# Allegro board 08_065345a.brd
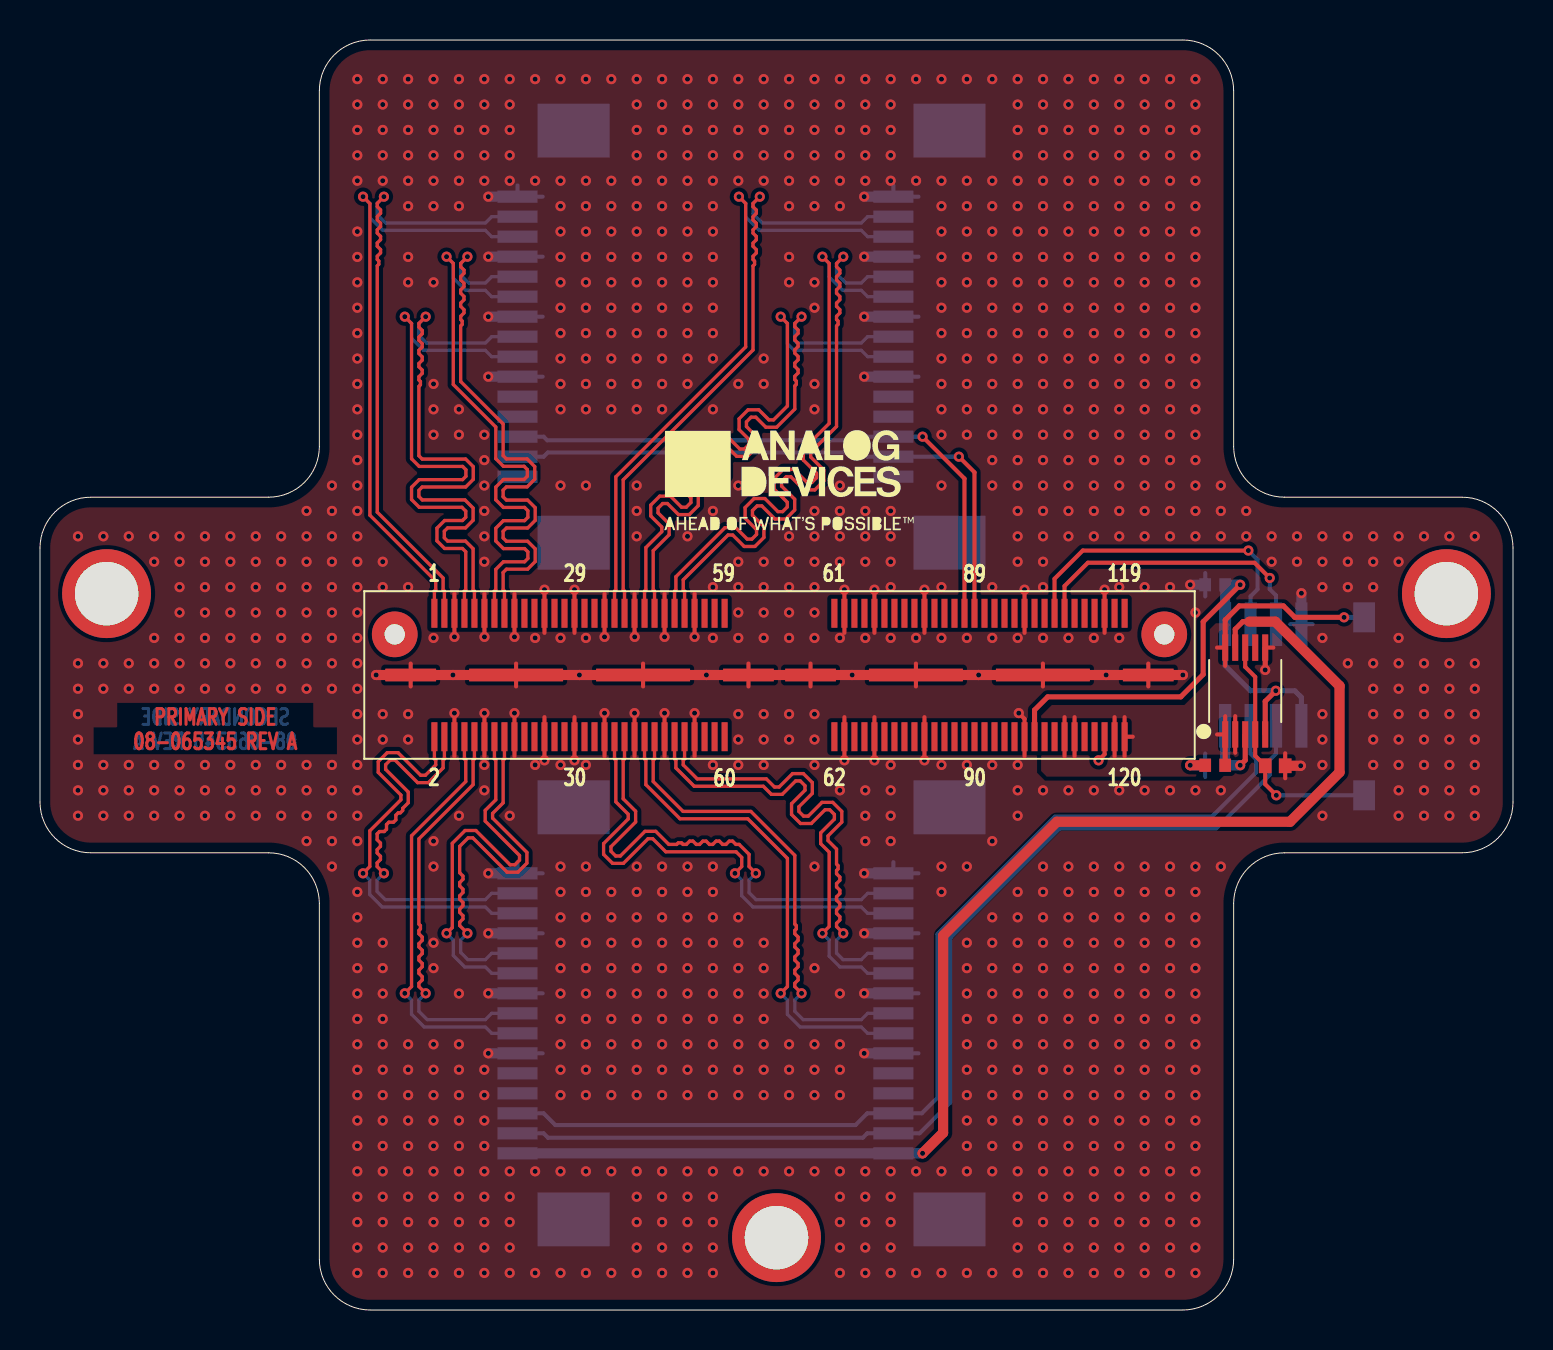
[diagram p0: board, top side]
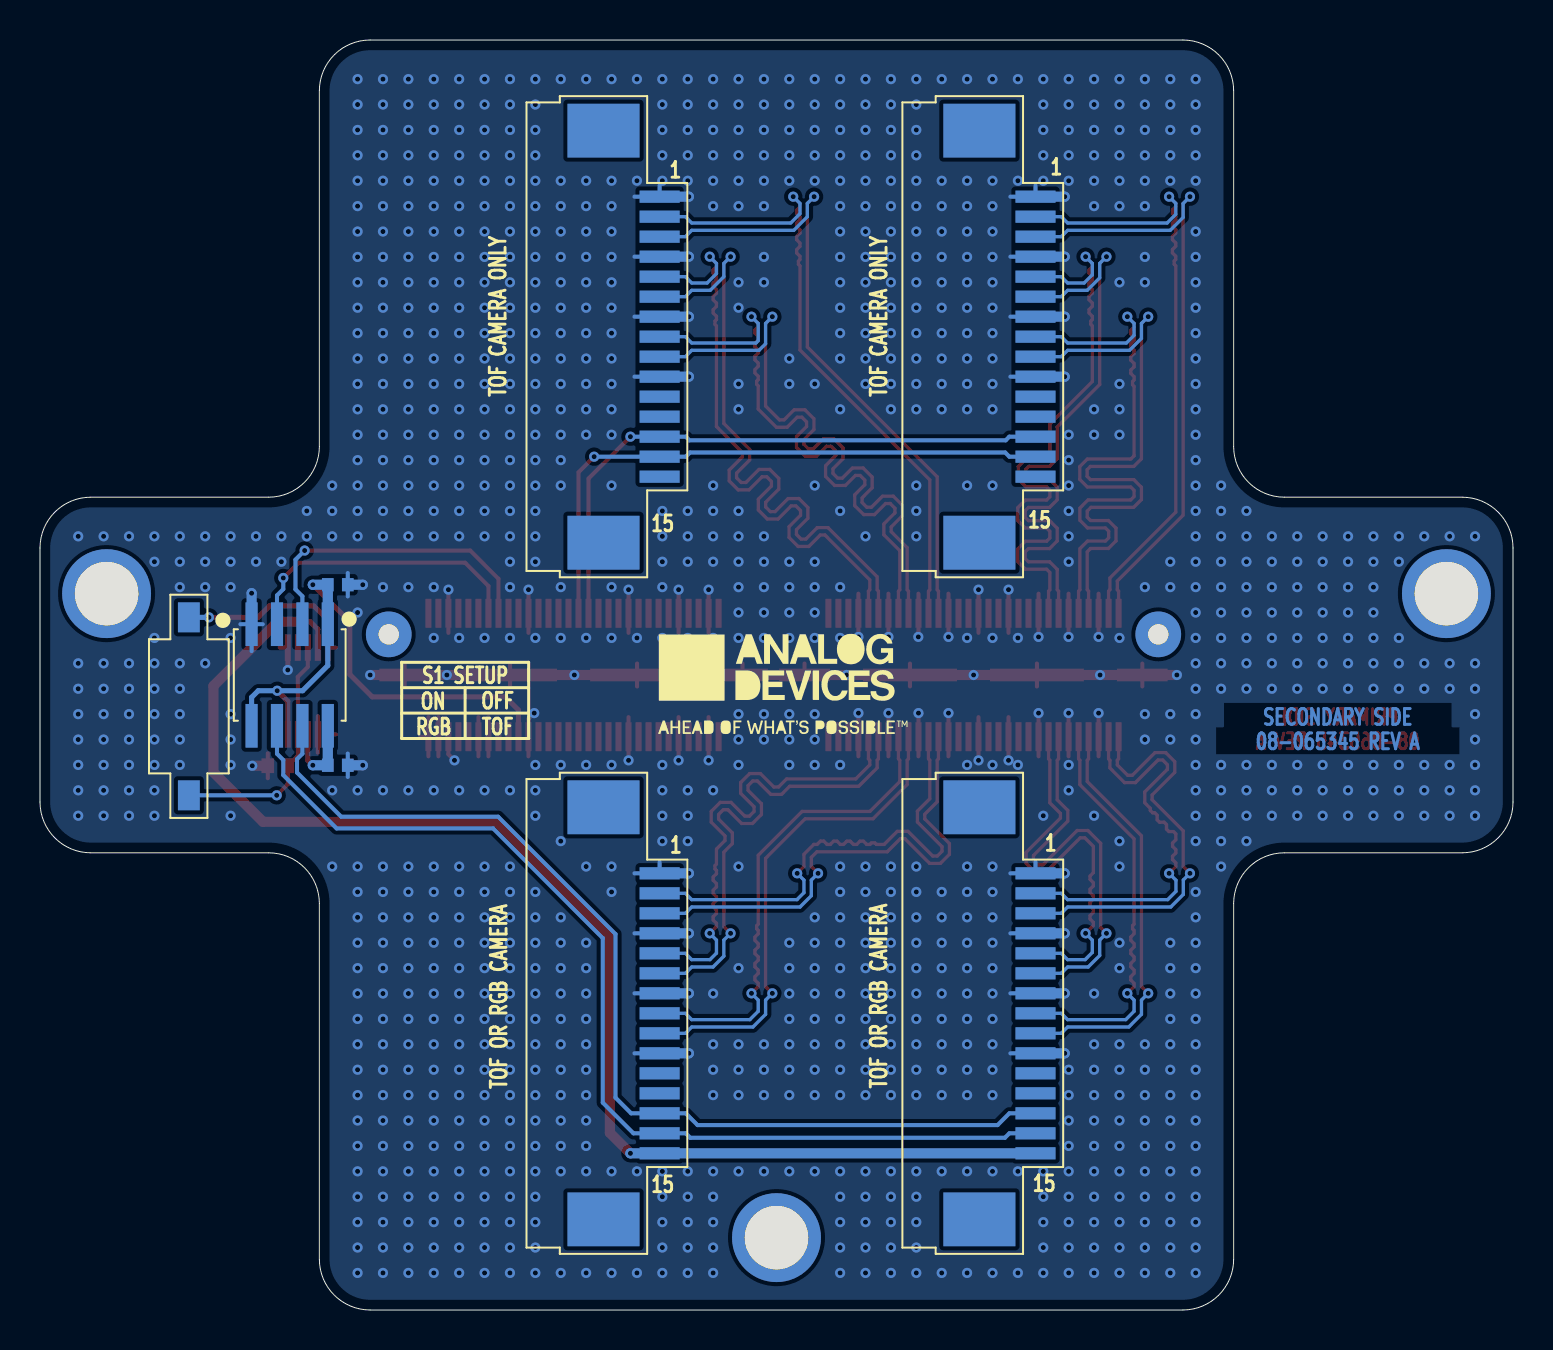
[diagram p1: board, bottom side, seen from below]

Outline 73.66 x 63.5 mm; copper layers: TOP, L2_GND, L3_GND, BOTTOM. Coordinates in mm from the lower left corner of the outline.
Outline path: 0,38.1 0,25.4 arc(0.74,23.6) 2.54,22.86 11.43,22.86 arc(13.23,22.12) 13.97,20.32 13.97,2.54 arc(14.71,0.74) 16.51,0 57.15,0 arc(58.95,0.74) 59.69,2.54 59.69,20.32 arc(60.43,22.12) 62.23,22.86 71.12,22.86 arc(72.92,23.6) 73.66,25.4 73.66,38.1 arc(72.92,39.9) 71.12,40.64 62.23,40.64 arc(60.43,41.38) 59.69,43.18 59.69,60.96 arc(58.95,62.76) 57.15,63.5 16.51,63.5 arc(14.71,62.76) 13.97,60.96 13.97,43.18 arc(13.23,41.38) 11.43,40.64 2.54,40.64 arc(0.74,39.9) 0,38.1

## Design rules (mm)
constraint set DEFAULT: min track width 0.203
net group CSI_0: nets CSI_0_CLK_N CSI_0_CLK_P CSI_0_D0_N CSI_0_D0_P CSI_0_D1_N CSI_0_D1_P
net group CSI_1: nets CSI_1_CLK_N CSI_1_CLK_P CSI_1_D0_N CSI_1_D0_P CSI_1_D1_N CSI_1_D1_P
net group CSI_4: nets CSI_4_CLK_N CSI_4_CLK_P CSI_4_D0_N CSI_4_D0_P CSI_4_D1_N CSI_4_D1_P
net group CSI_6: nets CSI_6_CLK_N CSI_6_CLK_P CSI_6_D0_N CSI_6_D0_P CSI_6_D1_N CSI_6_D1_P

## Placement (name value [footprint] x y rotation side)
C1  0.1UF  [C0402]  58.77 27.24 0 bottom
C2  0.1UF  [C0402]  58.77 36.26 180 bottom
C3  0.1UF  [C0402]  58.77 27.24 0 top
NOREF  -  [unnamed]  70.33 35.82 0 top
NOREF#2  -  [#2]  -39.37 318.77 0 top
NOREF#3  -  [#2]  73.66 22.86 90 top
NOREF#4  -  [#2]  406.4 71.12 0 top
NOREF#5  -  [#2]  73.66 40.64 180 top
NOREF#6  -  [#2]  142.24 74.93 270 top
NOREF#7  -  [unnamed]  36.83 3.62 0 top
NOREF#8  -  [#2]  -223.52 -132.08 0 top
NOREF#9  -  [#2]  406.4 10.16 0 top
NOREF#10  -  [#2]  0 40.64 270 top
NOREF#11  -  [#2]  37.16 41.45 0 top
NOREF#12  -  [#2]  -223.52 -132.08 0 top
NOREF#13  -  [unnamed]  3.33 35.82 0 top
NOREF#14  -  [#2]  -223.52 -132.08 0 top
NOREF#15  -  [#2]  142.24 113.03 0 top
NOREF#16  -  [#2]  0 22.86 0 top
NOREF#17  -  [#2]  87.63 293.37 0 top
NOREF#18  -  [#2]  176.53 318.77 0 top
NOREF#19  -  [#2]  36.8 31.27 180 bottom
NOREF#20  -  [#2]  145.43 306.07 180 bottom
NOREF#21  -  [#2]  157.49 26.04 180 bottom
P1  QTH-060-01-F-D-A  [CNSAMTECQTH-060-01-L-D-A]  36.98 31.75 0 top
P2  1-84952-5  [CNTE1-84952-5]  27.58 48.67 270 bottom
P3  1-84952-5  [CNTE1-84952-5]  46.38 48.67 270 bottom
P4  1-84952-5  [CNTE1-84952-5]  46.38 14.83 270 bottom
P5  1-84952-5  [CNTE1-84952-5]  27.58 14.83 270 bottom
R1  10K  [R0402]  61.77 27.21 0 top
S1  A6S-1104-H  [SWSML137W244H177]  66.22 30.18 0 bottom
U1  NLSX4373DR2G  [SO8]  61.17 31.75 0 bottom
U2  ADG884BRMZ  [RM10]  60.27 30.95 0 top

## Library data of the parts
C1-C3 = CAP: User Part Number: UPN; Tolerance: 10; alternate symbols: (); part number: CAP_SM-0.1UF,16V,10,E028141,C0402; tolerance: 10
P1 = CN120P_ODD_EVEN_8GND: Tolerance: N/A; User Part Number: UPN; alternate symbols: (); part number: CN120P_ODD_EVEN_8GND_SM-QTH-060-01-F-D-A,E025712,CNSAMTECQTH-060-01-L-D-A; tolerance: N/A
P2-P5 = CN15P: User Part Number: UPN; Tolerance: N/A; alternate symbols: (); part number: CN15P_SM-1-84952-5,E026042,CNTE1-84952-5; tolerance: N/A
R1 = RES: User Part Number: UPN; Tolerance: 1; alternate symbols: (R0402L,R0402L_ALT); part number: RES_SM-10K,E003751,1/10W,1,R0402; tolerance: 1
S1 = SWSPST2PIN_V4: User Part Number: UPN; Tolerance: N/A; alternate symbols: (); part number: SWSPST2PIN_V4_SM-A6S-1104-H,E025110,SWSML137W244H177; tolerance: N/A
U1 = ICNLSX4373: Tolerance: N/A; User Part Number: UPN; alternate symbols: (); part number: ICNLSX4373_SM-NLSX4373DR2G,E021744,SO8; tolerance: N/A
U2 = ADG884_V2: Tolerance: N/A; User Part Number: UPN; alternate symbols: (); part number: ADG884_V2_SM-ADG884BRMZ,E014585,RM10; tolerance: N/A

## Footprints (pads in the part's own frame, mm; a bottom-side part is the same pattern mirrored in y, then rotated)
C0402
  rect 0.584x0.66 smd: 1(-0.5,0) 2(0.5,0)
CNSAMTECQTH-060-01-L-D-A
  round 2.286 hole 1.016 unplated: (-19.241,2.032) (19.241,2.032)
  rect 0.305x1.448 smd: 1(-17.257,3.086) 2(-17.257,-3.086) 3(-16.756,3.086) 4(-16.756,-3.086) 5(-16.256,3.086) 6(-16.256,-3.086) 7(-15.756,3.086) 8(-15.756,-3.086) 9(-15.255,3.086) 10(-15.255,-3.086) 11(-14.755,3.086) 12(-14.755,-3.086) 13(-14.254,3.086) 14(-14.254,-3.086) 15(-13.754,3.086) 16(-13.754,-3.086) 17(-13.254,3.086) 18(-13.254,-3.086) 19(-12.753,3.086) 20(-12.753,-3.086) 21(-12.253,3.086) 22(-12.253,-3.086) 23(-11.753,3.086) 24(-11.753,-3.086) 25(-11.252,3.086) 26(-11.252,-3.086) 27(-10.752,3.086) 28(-10.752,-3.086) 29(-10.251,3.086) 30(-10.251,-3.086) 31(-9.751,3.086) 32(-9.751,-3.086) 33(-9.251,3.086) 34(-9.251,-3.086) 35(-8.75,3.086) 36(-8.75,-3.086) 37(-8.25,3.086) 38(-8.25,-3.086) 39(-7.75,3.086) 40(-7.75,-3.086) 41(-7.249,3.086) 42(-7.249,-3.086) 43(-6.749,3.086) 44(-6.749,-3.086) 45(-6.248,3.086) 46(-6.248,-3.086) 47(-5.748,3.086) 48(-5.748,-3.086) 49(-5.248,3.086) 50(-5.248,-3.086) 51(-4.747,3.086) 52(-4.747,-3.086) 53(-4.247,3.086) 54(-4.247,-3.086) 55(-3.747,3.086) 56(-3.747,-3.086) 57(-3.246,3.086) 58(-3.246,-3.086) 59(-2.746,3.086) 60(-2.746,-3.086) 61(2.746,3.086) 62(2.746,-3.086) 63(3.246,3.086) 64(3.246,-3.086) 65(3.747,3.086) 66(3.747,-3.086) 67(4.247,3.086) 68(4.247,-3.086) 69(4.747,3.086) 70(4.747,-3.086) 71(5.248,3.086) 72(5.248,-3.086) 73(5.748,3.086) 74(5.748,-3.086) 75(6.248,3.086) 76(6.248,-3.086) 77(6.749,3.086) 78(6.749,-3.086) 79(7.249,3.086) 80(7.249,-3.086) 81(7.75,3.086) 82(7.75,-3.086) 83(8.25,3.086) 84(8.25,-3.086) 85(8.75,3.086) 86(8.75,-3.086) 87(9.251,3.086) 88(9.251,-3.086) 89(9.751,3.086) 90(9.751,-3.086) 91(10.251,3.086) 92(10.251,-3.086) 93(10.752,3.086) 94(10.752,-3.086) 95(11.252,3.086) 96(11.252,-3.086) 97(11.753,3.086) 98(11.753,-3.086) 99(12.253,3.086) 100(12.253,-3.086) 101(12.753,3.086) 102(12.753,-3.086) 103(13.254,3.086) 104(13.254,-3.086) 105(13.754,3.086) 106(13.754,-3.086) 107(14.254,3.086) 108(14.254,-3.086) 109(14.755,3.086) 110(14.755,-3.086) 111(15.255,3.086) 112(15.255,-3.086) 113(15.756,3.086) 114(15.756,-3.086) 115(16.256,3.086) 116(16.256,-3.086) 117(16.756,3.086) 118(16.756,-3.086) 119(17.257,3.086) 120(17.257,-3.086)
  rect 2.54x0.635 smd: PAD1(-18.443,0) PAD4(-1.552,0) PAD5(1.552,0) PAD8(18.443,0)
  rect 4.699x0.635 smd: PAD2(-13.172,0) PAD3(-6.822,0) PAD6(6.822,0) PAD7(13.172,0)
CNTE1-84952-5
  rect 2.692x3.607 smd: (-10.301,0.897) (10.301,0.897)
  rect 0.61x2.007 smd: 1(-7,3.703) 2(-6,3.703) 3(-5,3.703) 4(-4,3.703) 5(-3,3.703) 6(-2,3.703) 7(-1,3.703) 8(0,3.703) 9(1,3.703) 10(2,3.703) 11(3,3.703) 12(4,3.703) 13(5,3.703) 14(6,3.703) 15(7,3.703)
R0402
  rect 0.635x0.737 smd: 1(-0.5,0) 2(0.5,0)
RM10
  rect 0.305x1.321 smd: 1(-1,-2.171) 2(-0.5,-2.171) 3(0,-2.171) 4(0.5,-2.171) 5(1,-2.171) 6(1,2.171) 7(0.5,2.171) 8(0,2.171) 9(-0.5,2.171) 10(-1,2.171)
SO8
  rect 0.61x2.184 smd: 1(-1.905,-2.54) 2(-0.635,-2.54) 3(0.635,-2.54) 4(1.905,-2.54) 5(1.905,2.54) 6(0.635,2.54) 7(-0.635,2.54) 8(-1.905,2.54)
SWSML137W244H177
  rect 1.092x1.499 smd: 1A(0,-4.449) 1B(0,4.449)
unnamed
  round 4.445 hole 3.175 unplated: (0,0)

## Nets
GND: C1.1 C2.2(N2) C3.1 P1.5 P1.6 P1.11 P1.12 P1.17 P1.18 P1.23 P1.24 P1.29 P1.30 P1.35 P1.36 P1.41 P1.42 P1.47 P1.48 P1.53 P1.54 P1.63 P1.64 P1.69 P1.70 P1.79 P1.80 P1.99 P1.100 P1.115 P1.116 P1.PAD1 P1.PAD2 P1.PAD3 P1.PAD4 P1.PAD5 P1.PAD6 P1.PAD7 P1.PAD8 P2.1 P2.4 P2.7 P2.10 P3.1 P3.4 P3.7 P3.10 P4.1 P4.4 P4.7 P4.10 P5.1 P5.4 P5.7 P5.10 R1.2(N2) U1.4 U2.6
VDD_1V8: C2.1 P1.102 U1.1(VL) U1.5 U2.5
VDD_3V3: C3.2(N2) P1.108 P1.110 P1.118 P1.120 S1.1A U2.1(VDD) U2.2 U2.10
CAM_3V3: P4.15 P5.15 U2.9
CSI_0_CLK_N: P1.9 P2.8
CSI_0_CLK_P: P1.7 P2.9(N9)
CSI_0_D0_N: P1.3 P2.2
CSI_0_D0_P: P1.1 P2.3
CSI_0_D1_N: P1.15 P2.5
CSI_0_D1_P: P1.13 P2.6
CSI_1_CLK_N: P1.10 P5.8
CSI_1_CLK_P: P1.8 P5.9(N9)
CSI_1_D0_N: P1.4 P5.2
CSI_1_D0_P: P1.2 P5.3
CSI_1_D1_N: P1.16 P5.5
CSI_1_D1_P: P1.14 P5.6
CSI_4_CLK_N: P1.45 P3.8
CSI_4_CLK_P: P1.43 P3.9(N9)
CSI_4_D0_N: P1.39 P3.2
CSI_4_D0_P: P1.37 P3.3
CSI_4_D1_N: P1.51 P3.5
CSI_4_D1_P: P1.49 P3.6
CSI_6_CLK_N: P1.46 P4.8
CSI_6_CLK_P: P1.44 P4.9(N9)
CSI_6_D0_N: P1.40 P4.2
CSI_6_D0_P: P1.38 P4.3
CSI_6_D1_N: P1.52 P4.5
CSI_6_D1_P: P1.50 P4.6
GP2_SCL: P1.87 P2.13 P3.13
GP2_SDA: P1.89 P2.14 P3.14
GP4_SCL: P1.105 U1.2
GP4_SDA: P1.107 U1.3
SCL: P4.13 P5.13 U1.7
SDA: P4.14 P5.14 U1.6
UNNAMED_2_ADG884V2_I42_D1: C1.2(N2) U1.8 U2.3
UNNAMED_2_ADG884V2_I42_IN1: R1.1 S1.1B(N2) U2.4 U2.8

Pads without a net: P1 19 20 21 22 25 26 27 28 31 32 33 34 55 56 57 58 59 60 61 62 65 66 67 68 71 72 73 74 75 76 77 78 81 82 83 84 85 86 88 90 91 92 93 94 95 96 97 98 101 103 104 106 109 111 112 113 114 117 119; P2 11 12 15; P3 11 12 15; P4 11 12; P5 11 12; U2 7

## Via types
v1: diameter 0.508, hole 0.254, TOP to BOTTOM, 1166 vias

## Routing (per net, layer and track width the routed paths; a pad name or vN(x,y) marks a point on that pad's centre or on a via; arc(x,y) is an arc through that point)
GND: length 167.1
  TOP w0.203: 43.8,32.32 P1.PAD6 43.8,31.18 ; 20.72,35.81 P1.5 v1(20.72,33.66) ; v1(41.73,36.02) P1.69 41.73,33.86 ; v1(25.23,36.02) P1.23 25.23,33.86 ; 35.43,31.18 P1.PAD4 35.43,32.32 ; 38.53,31.18 P1.PAD5 38.53,32.32 ; 53.24,33.86 P1.115 v1(53.24,36.02) ; 50.15,31.18 P1.PAD7 50.15,32.32 ; 30.16,32.32 P1.PAD3 30.16,31.18 ; v1(22.23,29.84) P1.12 22.23,27.69 ; v1(40.23,27.48) P1.64 40.23,29.64 ; v1(44.23,36.02) P1.79 44.23,33.86 ; P1.116 53.24,27.79 v1(52.93,27.48) ; 26.73,29.64 P1.30 v1(26.73,27.48) ; v1(31.23,29.84) P1.48 31.23,27.69 ; 29.73,35.81 P1.41 29.73,33.87 29.74,33.86 v1(29.74,33.66) ; 44.23,29.64 P1.80 v1(44.23,27.48) ; v1(29.73,29.84) P1.42 29.73,27.69 ; 31.23,35.81 P1.47 v1(31.23,33.66) ; 23.73,35.81 P1.17 v1(23.73,33.66) ; 23.81,31.18 P1.PAD2 23.81,32.32 ; 41.73,29.64 P1.70 v1(41.73,27.48) ; 32.73,27.69 P1.54 v1(32.73,29.84) ; 55.42,32.32 P1.PAD8 55.42,31.18 ; v1(23.73,29.84) P1.18 23.73,27.69 ; v1(48.95,29.84) 49.23,29.56 P1.100 49.23,27.69 ; 32.73,35.81 P1.53 v1(32.73,33.66) ; v1(22.23,33.66) P1.11 22.23,35.81 ; v1(28.23,29.84) P1.36 28.23,27.69 ; 25.23,29.64 P1.24 v1(25.23,27.48) ; v1(40.23,36.02) P1.63 40.23,33.86 ; v1(20.72,29.84) P1.6 20.72,27.69 ; 18.54,32.32 P1.PAD1 18.54,31.18 ; v1(28.23,33.66) P1.35 28.23,35.81 ; 26.73,33.86 P1.29 v1(26.73,36.02) ; 49.23,33.86 P1.99 v1(49.23,36.02) ; 62.27,26.59 R1.2 62.27,27.83 ; U2.6 61.68,33.12
  TOP w0.254: U2.6 v1(61.27,32)
  TOP w0.508: v1(57.15,31.75) P1.PAD8 v1(53.31,31.75) P1.PAD7 v1(46.94,31.75) P1.PAD6 v1(40.61,31.75) P1.PAD5 P1.PAD4 v1(33.32,31.75) P1.PAD3 v1(26.97,31.75) P1.PAD2 v1(20.65,31.75) P1.PAD1 v1(16.81,31.75) ; C3.1 v1(57.52,27.24) ; R1.2 v1(63.04,27.21)
  BOTTOM w0.203: 23.88,56.23 P2.1 25.14,55.67 ; 58.27,26.65 C3.1 58.27,27.82 ; 58.27,36.85 C2.2 58.27,35.68 ; 43.93,55.67 P3.1 42.67,56.23 ; P4.7 43.93,15.83 ; P5.10 25.14,12.83 ; U1.4 63.64,34.29 ; U1.4 62.52,34.29 ; U1.4 63.08,32.94 ; P5.4 25.14,18.83 ; P5.7 25.14,15.83 ; P3.10 43.93,46.67 ; P4.4 43.93,18.83 ; P2.7 25.14,49.67 ; P4.10 43.93,12.83 ; 43.93,21.83 P4.1 42.67,22.39 ; P2.4 25.14,52.67 ; P3.7 43.93,49.67 ; P3.4 43.93,52.67 ; P2.10 25.14,46.67 ; 25.14,21.83 P5.1 23.88,22.39
  BOTTOM w0.508: U1.4 v1(63.08,35.84) ; P3.1 v1(41.21,55.67) ; P2.1 v1(22.42,55.67) ; P2.4 v1(22.42,52.67) ; P4.10 v1(41.21,12.83) ; P2.10 v1(22.42,46.67) ; P4.4 v1(41.21,18.83) ; P5.4 v1(22.42,18.83) ; P4.7 v1(41.21,15.83) ; P2.7 v1(22.42,49.67) ; P3.7 v1(41.21,49.67) ; P3.10 v1(41.21,46.67) ; C3.1 v1(57.52,27.24) ; P5.10 v1(22.42,12.83) ; P5.1 v1(22.42,21.83) ; C2.2 v1(57.52,36.26) ; P4.1 v1(41.21,21.83) ; P5.7 v1(22.42,15.83) ; P3.4 v1(41.21,52.67)
  vias: v1(1.9,38.68) v1(1.9,32.33) v1(1.9,31.06) v1(1.9,29.79) v1(1.9,28.52) v1(1.9,27.25) v1(1.9,25.98) v1(1.9,24.71) v1(3.17,38.68) v1(3.17,32.33) v1(3.17,31.06) v1(3.17,27.25) v1(3.17,25.98) v1(3.17,24.71) v1(4.44,38.68) v1(4.44,32.33) v1(4.44,31.06) v1(4.44,27.25) v1(4.44,25.98) v1(4.44,24.71) v1(5.71,38.68) v1(5.71,37.41) v1(5.71,33.6) v1(5.71,32.33) v1(5.71,31.06) v1(5.71,27.25) v1(5.71,25.98) v1(5.71,24.71) v1(6.98,38.68) v1(6.98,37.41) v1(6.98,36.14) v1(6.98,34.87) v1(6.98,33.6) v1(6.98,32.33) v1(6.98,31.06) v1(6.98,27.25) v1(6.98,25.98) v1(6.98,24.71) v1(8.25,38.68) v1(8.25,37.41) v1(8.25,36.14) v1(8.25,34.87) v1(8.25,33.6) v1(8.25,32.33) v1(8.25,31.06) v1(8.25,27.25) v1(8.25,25.98) v1(8.25,24.71) v1(9.52,38.68) v1(9.52,37.41) v1(9.52,36.14) v1(9.52,34.87) v1(9.52,33.6) v1(9.52,32.33) v1(9.52,31.06) v1(9.52,27.25) v1(9.52,25.98) v1(9.52,24.71) v1(10.79,38.68) v1(10.79,37.41) v1(10.79,36.14) v1(10.79,34.87) v1(10.79,33.6) v1(10.79,32.33) v1(10.79,31.06) v1(10.79,27.25) v1(10.79,25.98) v1(10.79,24.71) v1(12.06,38.68) v1(12.06,37.41) v1(12.06,36.14) v1(12.06,34.87) v1(12.06,33.6) v1(12.06,32.33) v1(12.06,31.06) v1(12.06,27.25) v1(12.06,25.98) v1(12.06,24.71) v1(13.33,39.95) v1(13.33,38.68) v1(13.33,37.41) v1(13.33,36.14) v1(13.33,34.87) v1(13.33,33.6) v1(13.33,32.33) v1(13.33,31.06) v1(13.33,27.25) v1(13.33,25.98) v1(13.33,24.71) v1(13.33,23.44) v1(14.6,41.22) v1(14.6,39.95) v1(14.6,38.68) v1(14.6,37.41) v1(14.6,36.14) v1(14.6,34.87) v1(14.6,33.6) v1(14.6,32.33) v1(14.6,31.06) v1(14.6,27.25) v1(14.6,25.98) v1(14.6,24.71) v1(14.6,23.44) v1(14.6,22.17) v1(15.87,61.54) v1(15.87,60.27) v1(15.87,59) v1(15.87,57.73) v1(15.87,56.46) v1(15.87,53.92) v1(15.87,52.65) v1(15.87,51.38) v1(15.87,50.11) v1(15.87,48.84) v1(15.87,47.57) v1(15.87,46.3) v1(15.87,45.03) v1(15.87,43.76) v1(15.87,42.49) v1(15.87,41.22) v1(15.87,39.95) v1(15.87,38.68) v1(15.87,37.41) v1(15.87,36.14) v1(15.87,34.87) v1(15.87,33.6) v1(15.87,32.33) v1(15.87,31.06) v1(15.87,29.79) v1(15.87,28.52) v1(15.87,27.25) v1(15.87,25.98) v1(15.87,24.71) v1(15.87,23.44) v1(15.87,20.9) v1(15.87,19.63) v1(15.87,18.36) v1(15.87,17.09) v1(15.87,15.82) v1(15.87,14.55) v1(15.87,13.28) v1(15.87,12.01) v1(15.87,10.74) v1(15.87,9.47) v1(15.87,8.2) v1(15.87,6.93) v1(15.87,5.66) v1(15.87,4.39) v1(15.87,3.12) v1(15.87,1.85) v1(17.14,61.54) v1(17.14,60.27) v1(17.14,59) v1(17.14,57.73) v1(17.14,56.46) v1(17.14,37.41) v1(17.14,36.14) v1(17.14,29.79) v1(17.14,28.52) v1(17.14,18.36) v1(17.14,17.09) v1(17.14,15.82) v1(17.14,14.55) v1(17.14,13.28) v1(17.14,12.01) v1(17.14,10.74) v1(17.14,9.47) v1(17.14,8.2) v1(17.14,6.93) v1(17.14,5.66) v1(17.14,4.39) v1(17.14,3.12) v1(17.14,1.85) v1(18.41,61.54) v1(18.41,60.27) v1(18.41,59) v1(18.41,57.73) v1(18.41,56.46) v1(18.41,55.19) v1(18.41,52.65) v1(18.41,51.38) v1(18.41,36.14) v1(18.41,29.79) v1(18.41,28.52) v1(18.41,13.28) v1(18.41,12.01) v1(18.41,10.74) v1(18.41,9.47) v1(18.41,8.2) v1(18.41,6.93) v1(18.41,5.66) v1(18.41,4.39) v1(18.41,3.12) v1(18.41,1.85) v1(19.68,61.54) v1(19.68,60.27) v1(19.68,59) v1(19.68,57.73) v1(19.68,56.46) v1(19.68,55.19) v1(19.68,51.38) v1(19.68,46.3) v1(19.68,45.03) v1(19.68,43.76) v1(19.68,33.6) v1(19.68,23.44) v1(19.68,22.17) v1(19.68,18.36) v1(19.68,17.09) v1(19.68,13.28) v1(19.68,12.01) v1(19.68,10.74) v1(19.68,9.47) v1(19.68,8.2) v1(19.68,6.93) v1(19.68,5.66) v1(19.68,4.39) v1(19.68,3.12) v1(19.68,1.85) v1(20.95,61.54) v1(20.95,60.27) v1(20.95,59) v1(20.95,57.73) v1(20.95,56.46) v1(20.95,55.19) v1(20.95,45.03) v1(20.95,43.76) v1(20.95,24.71) v1(20.95,15.82) v1(20.95,13.28) v1(20.95,12.01) v1(20.95,10.74) v1(20.95,9.47) v1(20.95,8.2) v1(20.95,6.93) v1(20.95,5.66) v1(20.95,4.39) v1(20.95,3.12) v1(20.95,1.85) v1(22.22,61.54) v1(22.22,60.27) v1(22.22,59) v1(22.22,57.73) v1(22.22,56.46) v1(22.22,43.76) v1(22.22,42.49) v1(22.22,41.22) v1(22.22,39.95) v1(22.22,38.68) v1(22.22,37.41) v1(22.22,27.25) v1(22.22,25.98) v1(22.22,12.01) v1(22.22,10.74) v1(22.22,9.47) v1(22.22,8.2) v1(22.22,6.93) v1(22.22,5.66) v1(22.22,4.39) v1(22.22,3.12) v1(22.22,1.85) v1(23.49,61.54) v1(23.49,60.27) v1(23.49,59) v1(23.49,57.73) v1(23.49,56.46) v1(23.49,24.71) v1(23.49,6.93) v1(23.49,5.66) v1(23.49,4.39) v1(23.49,3.12) v1(23.49,1.85) v1(24.76,61.54) v1(24.76,56.46) v1(24.76,33.6) v1(24.76,27.25) v1(24.76,6.93) v1(24.76,1.85) v1(26.03,61.54) v1(26.03,56.46) v1(26.03,55.19) v1(26.03,53.92) v1(26.03,52.65) v1(26.03,51.38) v1(26.03,50.11) v1(26.03,48.84) v1(26.03,47.57) v1(26.03,46.3) v1(26.03,45.03) v1(26.03,41.22) v1(26.03,33.6) v1(26.03,27.25) v1(26.03,22.17) v1(26.03,20.9) v1(26.03,19.63) v1(26.03,18.36) v1(26.03,17.09) v1(26.03,15.82) v1(26.03,14.55) v1(26.03,13.28) v1(26.03,12.01) v1(26.03,10.74) v1(26.03,6.93) v1(26.03,1.85) v1(27.3,61.54) v1(27.3,56.46) v1(27.3,55.19) v1(27.3,53.92) v1(27.3,52.65) v1(27.3,51.38) v1(27.3,50.11) v1(27.3,48.84) v1(27.3,47.57) v1(27.3,46.3) v1(27.3,45.03) v1(27.3,41.22) v1(27.3,33.6) v1(27.3,27.25) v1(27.3,22.17) v1(27.3,20.9) v1(27.3,19.63) v1(27.3,18.36) v1(27.3,17.09) v1(27.3,15.82) v1(27.3,14.55) v1(27.3,13.28) v1(27.3,12.01) v1(27.3,10.74) v1(27.3,6.93) v1(27.3,1.85) v1(28.57,61.54) v1(28.57,56.46) v1(28.57,55.19) v1(28.57,53.92) v1(28.57,52.65) v1(28.57,51.38) v1(28.57,50.11) v1(28.57,48.84) v1(28.57,47.57) v1(28.57,46.3) v1(28.57,45.03) v1(28.57,20.9) v1(28.57,19.63) v1(28.57,18.36) v1(28.57,17.09) v1(28.57,15.82) v1(28.57,14.55) v1(28.57,13.28) v1(28.57,12.01) v1(28.57,10.74) v1(28.57,6.93) v1(28.57,1.85) v1(29.84,61.54) v1(29.84,60.27) v1(29.84,59) v1(29.84,57.73) v1(29.84,56.46) v1(29.84,55.19) v1(29.84,53.92) v1(29.84,52.65) v1(29.84,51.38) v1(29.84,50.11) v1(29.84,48.84) v1(29.84,47.57) v1(29.84,46.3) v1(29.84,45.03) v1(29.84,41.22) v1(29.84,39.95) v1(29.84,38.68) v1(29.84,22.17) v1(29.84,20.9) v1(29.84,19.63) v1(29.84,18.36) v1(29.84,17.09) v1(29.84,15.82) v1(29.84,14.55) v1(29.84,13.28) v1(29.84,12.01) v1(29.84,10.74) v1(29.84,6.93) v1(29.84,5.66) v1(29.84,4.39) v1(29.84,3.12) v1(29.84,1.85) v1(31.11,61.54) v1(31.11,60.27) v1(31.11,59) v1(31.11,57.73) v1(31.11,56.46) v1(31.11,55.19) v1(31.11,53.92) v1(31.11,52.65) v1(31.11,51.38) v1(31.11,50.11) v1(31.11,48.84) v1(31.11,47.57) v1(31.11,46.3) v1(31.11,45.03) v1(31.11,22.17) v1(31.11,20.9) v1(31.11,19.63) v1(31.11,18.36) v1(31.11,17.09) v1(31.11,15.82) v1(31.11,14.55) v1(31.11,13.28) v1(31.11,12.01) v1(31.11,10.74) v1(31.11,6.93) v1(31.11,5.66) v1(31.11,4.39) v1(31.11,3.12) v1(31.11,1.85) v1(32.38,61.54) v1(32.38,60.27) v1(32.38,59) v1(32.38,57.73) v1(32.38,56.46) v1(32.38,55.19) v1(32.38,53.92) v1(32.38,52.65) v1(32.38,51.38) v1(32.38,50.11) v1(32.38,48.84) v1(32.38,47.57) v1(32.38,46.3) v1(32.38,38.68) v1(32.38,22.17) v1(32.38,20.9) v1(32.38,19.63) v1(32.38,18.36) v1(32.38,17.09) v1(32.38,15.82) v1(32.38,14.55) v1(32.38,13.28) v1(32.38,12.01) v1(32.38,10.74) v1(32.38,6.93) v1(32.38,5.66) v1(32.38,4.39) v1(32.38,3.12) v1(32.38,1.85) v1(33.65,61.54) v1(33.65,60.27) v1(33.65,59) v1(33.65,57.73) v1(33.65,56.46) v1(33.65,55.19) v1(33.65,53.92) v1(33.65,52.65) v1(33.65,51.38) v1(33.65,50.11) v1(33.65,48.84) v1(33.65,47.57) v1(33.65,45.03) v1(33.65,39.95) v1(33.65,36.14) v1(33.65,33.6) v1(33.65,27.25) v1(33.65,22.17) v1(33.65,20.9) v1(33.65,19.63) v1(33.65,18.36) v1(33.65,17.09) v1(33.65,15.82) v1(33.65,14.55) v1(33.65,13.28) v1(33.65,12.01) v1(33.65,10.74) v1(33.65,6.93) v1(33.65,5.66) v1(33.65,4.39) v1(33.65,3.12) v1(33.65,1.85) v1(34.92,61.54) v1(34.92,60.27) v1(34.92,59) v1(34.92,57.73) v1(34.92,56.46) v1(34.92,46.3) v1(34.92,41.22) v1(34.92,37.41) v1(34.92,36.14) v1(34.92,34.87) v1(34.92,33.6) v1(34.92,29.79) v1(34.92,28.52) v1(34.92,27.25) v1(34.92,19.63) v1(34.92,18.36) v1(34.92,17.09) v1(34.92,15.82) v1(34.92,14.55) v1(34.92,13.28) v1(34.92,12.01) v1(34.92,10.74) v1(34.92,6.93) v1(36.19,61.54) v1(36.19,60.27) v1(36.19,59) v1(36.19,57.73) v1(36.19,56.46) v1(36.19,47.57) v1(36.19,46.3) v1(36.19,37.41) v1(36.19,36.14) v1(36.19,34.87) v1(36.19,33.6) v1(36.19,29.79) v1(36.19,28.52) v1(36.19,27.25) v1(36.19,18.36) v1(36.19,17.09) v1(36.19,15.82) v1(36.19,14.55) v1(36.19,13.28) v1(36.19,12.01) v1(36.19,10.74) v1(36.19,6.93) v1(37.46,61.54) v1(37.46,60.27) v1(37.46,59) v1(37.46,57.73) v1(37.46,56.46) v1(37.46,55.19) v1(37.46,52.65) v1(37.46,51.38) v1(37.46,38.68) v1(37.46,37.41) v1(37.46,36.14) v1(37.46,34.87) v1(37.46,33.6) v1(37.46,29.79) v1(37.46,28.52) v1(37.46,13.28) v1(37.46,12.01) v1(37.46,10.74) v1(37.46,6.93) v1(38.73,61.54) v1(38.73,60.27) v1(38.73,59) v1(38.73,57.73) v1(38.73,56.46) v1(38.73,55.19) v1(38.73,51.38) v1(38.73,50.11) v1(38.73,46.3) v1(38.73,45.03) v1(38.73,39.95) v1(38.73,38.68) v1(38.73,37.41) v1(38.73,36.14) v1(38.73,34.87) v1(38.73,33.6) v1(38.73,29.79) v1(38.73,28.52) v1(38.73,27.25) v1(38.73,22.17) v1(38.73,17.09) v1(38.73,13.28) v1(38.73,12.01) v1(38.73,10.74) v1(38.73,6.93) v1(40,61.54) v1(40,60.27) v1(40,59) v1(40,57.73) v1(40,56.46) v1(40,55.19) v1(40,41.22) v1(40,39.95) v1(40,38.68) v1(40,37.41) v1(40,33.6) v1(40,25.98) v1(40,15.82) v1(40,13.28) v1(40,12.01) v1(40,10.74) v1(40,6.93) v1(40,5.66) v1(40,4.39) v1(40,3.12) v1(40,1.85) v1(41.27,61.54) v1(41.27,60.27) v1(41.27,59) v1(41.27,57.73) v1(41.27,56.46) v1(41.27,39.95) v1(41.27,38.68) v1(41.27,37.41) v1(41.27,33.6) v1(41.27,25.98) v1(41.27,24.71) v1(41.27,23.44) v1(41.27,6.93) v1(41.27,5.66) v1(41.27,4.39) v1(41.27,3.12) v1(41.27,1.85) v1(42.54,61.54) v1(42.54,60.27) v1(42.54,59) v1(42.54,57.73) v1(42.54,56.46) v1(42.54,39.95) v1(42.54,38.68) v1(42.54,37.41) v1(42.54,36.14) v1(42.54,33.6) v1(42.54,27.25) v1(42.54,25.98) v1(42.54,24.71) v1(42.54,23.44) v1(42.54,6.93) v1(42.54,5.66) v1(42.54,4.39) v1(42.54,3.12) v1(42.54,1.85) v1(43.81,61.54) v1(43.81,56.46) v1(43.81,33.6) v1(43.81,6.93) v1(43.81,1.85) v1(45.08,61.54) v1(45.08,56.46) v1(45.08,55.19) v1(45.08,53.92) v1(45.08,52.65) v1(45.08,51.38) v1(45.08,50.11) v1(45.08,48.84) v1(45.08,47.57) v1(45.08,46.3) v1(45.08,45.03) v1(45.08,43.76) v1(45.08,41.22) v1(45.08,36.14) v1(45.08,33.6) v1(45.08,27.25) v1(45.08,22.17) v1(45.08,20.9) v1(45.08,6.93) v1(45.08,1.85) v1(46.35,61.54) v1(46.35,56.46) v1(46.35,55.19) v1(46.35,53.92) v1(46.35,52.65) v1(46.35,51.38) v1(46.35,50.11) v1(46.35,48.84) v1(46.35,47.57) v1(46.35,46.3) v1(46.35,45.03) v1(46.35,43.76) v1(46.35,33.6) v1(46.35,27.25) v1(46.35,22.17) v1(46.35,18.36) v1(46.35,17.09) v1(46.35,15.82) v1(46.35,14.55) v1(46.35,13.28) v1(46.35,12.01) v1(46.35,10.74) v1(46.35,9.47) v1(46.35,8.2) v1(46.35,6.93) v1(46.35,1.85) v1(47.62,61.54) v1(47.62,56.46) v1(47.62,55.19) v1(47.62,53.92) v1(47.62,52.65) v1(47.62,51.38) v1(47.62,50.11) v1(47.62,48.84) v1(47.62,47.57) v1(47.62,46.3) v1(47.62,45.03) v1(47.62,43.76) v1(47.62,42.49) v1(47.62,41.22) v1(47.62,36.14) v1(47.62,33.6) v1(47.62,27.25) v1(47.62,23.44) v1(47.62,19.63) v1(47.62,18.36) v1(47.62,17.09) v1(47.62,15.82) v1(47.62,14.55) v1(47.62,13.28) v1(47.62,12.01) v1(47.62,10.74) v1(47.62,9.47) v1(47.62,8.2) v1(47.62,6.93) v1(47.62,1.85) v1(48.89,61.54) v1(48.89,60.27) v1(48.89,59) v1(48.89,57.73) v1(48.89,56.46) v1(48.89,55.19) v1(48.89,53.92) v1(48.89,52.65) v1(48.89,51.38) v1(48.89,50.11) v1(48.89,48.84) v1(48.89,47.57) v1(48.89,46.3) v1(48.89,45.03) v1(48.89,43.76) v1(48.89,42.49) v1(48.89,41.22) v1(48.89,39.95) v1(48.89,38.68) v1(48.89,37.41) v1(48.89,33.6) v1(48.89,27.25) v1(48.89,25.98) v1(48.89,24.71) v1(48.89,20.9) v1(48.89,19.63) v1(48.89,18.36) v1(48.89,17.09) v1(48.89,15.82) v1(48.89,14.55) v1(48.89,13.28) v1(48.89,12.01) v1(48.89,10.74) v1(48.89,9.47) v1(48.89,8.2) v1(48.89,6.93) v1(48.89,5.66) v1(48.89,4.39) v1(48.89,3.12) v1(48.89,1.85) v1(50.16,61.54) v1(50.16,60.27) v1(50.16,59) v1(50.16,57.73) v1(50.16,56.46) v1(50.16,55.19) v1(50.16,53.92) v1(50.16,52.65) v1(50.16,51.38) v1(50.16,50.11) v1(50.16,48.84) v1(50.16,47.57) v1(50.16,46.3) v1(50.16,45.03) v1(50.16,43.76) v1(50.16,42.49) v1(50.16,41.22) v1(50.16,39.95) v1(50.16,38.68) v1(50.16,37.41) v1(50.16,36.14) v1(50.16,33.6) v1(50.16,25.98) v1(50.16,22.17) v1(50.16,20.9) v1(50.16,19.63) v1(50.16,18.36) v1(50.16,17.09) v1(50.16,15.82) v1(50.16,14.55) v1(50.16,13.28) v1(50.16,12.01) v1(50.16,10.74) v1(50.16,9.47) v1(50.16,8.2) v1(50.16,6.93) v1(50.16,5.66) v1(50.16,4.39) v1(50.16,3.12) v1(50.16,1.85) v1(51.43,61.54) v1(51.43,60.27) v1(51.43,59) v1(51.43,57.73) v1(51.43,56.46) v1(51.43,55.19) v1(51.43,53.92) v1(51.43,52.65) v1(51.43,51.38) v1(51.43,50.11) v1(51.43,48.84) v1(51.43,47.57) v1(51.43,46.3) v1(51.43,45.03) v1(51.43,43.76) v1(51.43,42.49) v1(51.43,41.22) v1(51.43,39.95) v1(51.43,38.68) v1(51.43,33.6) v1(51.43,25.98) v1(51.43,22.17) v1(51.43,20.9) v1(51.43,19.63) v1(51.43,18.36) v1(51.43,17.09) v1(51.43,15.82) v1(51.43,14.55) v1(51.43,13.28) v1(51.43,12.01) v1(51.43,10.74) v1(51.43,9.47) v1(51.43,8.2) v1(51.43,6.93) v1(51.43,5.66) v1(51.43,4.39) v1(51.43,3.12) v1(51.43,1.85) v1(52.7,61.54) v1(52.7,60.27) v1(52.7,59) v1(52.7,57.73) v1(52.7,56.46) v1(52.7,55.19) v1(52.7,53.92) v1(52.7,52.65) v1(52.7,51.38) v1(52.7,50.11) v1(52.7,48.84) v1(52.7,47.57) v1(52.7,46.3) v1(52.7,45.03) v1(52.7,43.76) v1(52.7,42.49) v1(52.7,41.22) v1(52.7,39.95) v1(52.7,38.68) v1(52.7,33.6) v1(52.7,25.98) v1(52.7,22.17) v1(52.7,20.9) v1(52.7,19.63) v1(52.7,18.36) v1(52.7,17.09) v1(52.7,15.82) v1(52.7,14.55) v1(52.7,13.28) v1(52.7,12.01) v1(52.7,10.74) v1(52.7,9.47) v1(52.7,8.2) v1(52.7,6.93) v1(52.7,5.66) v1(52.7,4.39) v1(52.7,3.12) v1(52.7,1.85) v1(53.97,61.54) v1(53.97,60.27) v1(53.97,59) v1(53.97,57.73) v1(53.97,56.46) v1(53.97,55.19) v1(53.97,53.92) v1(53.97,52.65) v1(53.97,51.38) v1(53.97,50.11) v1(53.97,48.84) v1(53.97,47.57) v1(53.97,46.3) v1(53.97,45.03) v1(53.97,43.76) v1(53.97,42.49) v1(53.97,41.22) v1(53.97,39.95) v1(53.97,38.68) v1(53.97,36.14) v1(53.97,33.6) v1(53.97,25.98) v1(53.97,22.17) v1(53.97,20.9) v1(53.97,19.63) v1(53.97,18.36) v1(53.97,17.09) v1(53.97,15.82) v1(53.97,14.55) v1(53.97,13.28) v1(53.97,12.01) v1(53.97,10.74) v1(53.97,9.47) v1(53.97,8.2) v1(53.97,6.93) v1(53.97,5.66) v1(53.97,4.39) v1(53.97,3.12) v1(53.97,1.85) v1(55.24,61.54) v1(55.24,60.27) v1(55.24,59) v1(55.24,57.73) v1(55.24,56.46) v1(55.24,55.19) v1(55.24,53.92) v1(55.24,52.65) v1(55.24,51.38) v1(55.24,50.11) v1(55.24,48.84) v1(55.24,47.57) v1(55.24,46.3) v1(55.24,45.03) v1(55.24,43.76) v1(55.24,42.49) v1(55.24,41.22) v1(55.24,39.95) v1(55.24,38.68) v1(55.24,36.14) v1(55.24,25.98) v1(55.24,22.17) v1(55.24,20.9) v1(55.24,19.63) v1(55.24,18.36) v1(55.24,17.09) v1(55.24,15.82) v1(55.24,14.55) v1(55.24,13.28) v1(55.24,12.01) v1(55.24,10.74) v1(55.24,9.47) v1(55.24,8.2) v1(55.24,6.93) v1(55.24,5.66) v1(55.24,4.39) v1(55.24,3.12) v1(55.24,1.85) v1(56.51,61.54) v1(56.51,60.27) v1(56.51,59) v1(56.51,57.73) v1(56.51,56.46) v1(56.51,55.19) v1(56.51,53.92) v1(56.51,52.65) v1(56.51,51.38) v1(56.51,50.11) v1(56.51,48.84) v1(56.51,47.57) v1(56.51,46.3) v1(56.51,45.03) v1(56.51,43.76) v1(56.51,42.49) v1(56.51,41.22) v1(56.51,39.95) v1(56.51,38.68) v1(56.51,36.14) v1(56.51,25.98) v1(56.51,22.17) v1(56.51,20.9) v1(56.51,19.63) v1(56.51,18.36) v1(56.51,17.09) v1(56.51,15.82) v1(56.51,14.55) v1(56.51,13.28) v1(56.51,12.01) v1(56.51,10.74) v1(56.51,9.47) v1(56.51,8.2) v1(56.51,6.93) v1(56.51,5.66) v1(56.51,4.39) v1(56.51,3.12) v1(56.51,1.85) v1(57.78,61.54) v1(57.78,60.27) v1(57.78,59) v1(57.78,57.73) v1(57.78,56.46) v1(57.78,55.19) v1(57.78,53.92) v1(57.78,52.65) v1(57.78,51.38) v1(57.78,50.11) v1(57.78,48.84) v1(57.78,47.57) v1(57.78,46.3) v1(57.78,45.03) v1(57.78,43.76) v1(57.78,42.49) v1(57.78,41.22) v1(57.78,39.95) v1(57.78,38.68) v1(57.78,34.87) v1(57.78,25.98) v1(57.78,22.17) v1(57.78,20.9) v1(57.78,19.63) v1(57.78,18.36) v1(57.78,17.09) v1(57.78,15.82) v1(57.78,14.55) v1(57.78,13.28) v1(57.78,12.01) v1(57.78,10.74) v1(57.78,9.47) v1(57.78,8.2) v1(57.78,6.93) v1(57.78,5.66) v1(57.78,4.39) v1(57.78,3.12) v1(57.78,1.85) v1(59.05,41.22) v1(59.05,39.95) v1(59.05,38.68) v1(59.05,25.98) v1(59.05,22.17) v1(60.32,39.95) v1(60.32,38.68) v1(61.59,38.68) v1(61.59,37.41) v1(62.86,38.68) v1(62.86,37.41) v1(64.13,38.68) v1(64.13,37.41) v1(64.13,36.14) v1(64.13,33.6) v1(64.13,29.79) v1(64.13,28.52) v1(64.13,27.25) v1(64.13,24.71) v1(65.4,38.68) v1(65.4,37.41) v1(65.4,36.14) v1(65.4,32.33) v1(66.67,38.68) v1(66.67,37.41) v1(66.67,36.14) v1(66.67,32.33) v1(66.67,31.06) v1(66.67,29.79) v1(66.67,28.52) v1(66.67,27.25) v1(67.94,38.68) v1(67.94,37.41) v1(67.94,33.6) v1(67.94,32.33) v1(67.94,31.06) v1(67.94,29.79) v1(67.94,28.52) v1(67.94,27.25) v1(67.94,25.98) v1(67.94,24.71) v1(69.21,38.68) v1(69.21,32.33) v1(69.21,31.06) v1(69.21,29.79) v1(69.21,28.52) v1(69.21,27.25) v1(69.21,25.98) v1(69.21,24.71) v1(70.48,38.68) v1(70.48,32.33) v1(70.48,31.06) v1(70.48,29.79) v1(70.48,28.52) v1(70.48,27.25) v1(70.48,25.98) v1(70.48,24.71) v1(71.75,38.68) v1(71.75,32.33) v1(71.75,31.06) v1(71.75,29.79) v1(71.75,28.52) v1(71.75,27.25) v1(71.75,25.98) v1(71.75,24.71)
VDD_1V8: length 28.8
  TOP w0.254: v1(61.8,30.96) 61.27,30.43 U2.5 ; P1.102 49.73,30 50.39,30.66 57.05,30.66 58.17,31.78 58.17,34.41 v1(60.02,36.26)
  BOTTOM w0.254: U1.5 63.08,30.63 62.75,30.96 v1(61.8,30.96) 60.53,30.96 59.27,32.22 U1.1
  BOTTOM w0.508: v1(60.02,36.26) C2.1 U1.1
VDD_3V3: length 23.1
  TOP w0.203: 53.74,27.69 P1.118 53.74,29.64 ; 59.77,27.86 U2.2 59.77,29.69 ; P1.120 54.24,29.64 ; P1.120 54.24,27.69 ; P1.120 54.64,28.66 ; 59.27,29.69 U2.1 58.86,28.78 ; 51.73,27.69 P1.110 51.73,29.64 ; 59.27,32.21 U2.10 58.86,33.12 ; 51.23,29.64 P1.108 51.23,27.69
  TOP w0.254: v1(65.21,34.63) 62.75,34.63 62.18,35.2 59.97,35.2 59.27,34.5 U2.10 ; C3.2 U2.1
  BOTTOM w0.254: v1(65.21,34.63) S1.1A
CAM_3V3: length 66.7
  TOP w0.254: U2.9 59.77,34.04 60.15,34.42 60.48,34.42
  TOP w0.508: v1(44.14,7.83) 45.16,8.86 45.16,18.72 50.85,24.41 62.51,24.41 64.99,26.89 64.99,31.2 61.77,34.42 60.48,34.42
  BOTTOM w0.508: v1(44.14,7.83) P4.15 P5.15
CSI_0_CLK_N: length 31.3
  TOP w0.165: v1(19.29,49.67) 18.95,49.33 18.95,49.14 19.11,48.98 19.11,48.81 18.95,48.65 18.95,48.48 19.11,48.32 19.11,48.15 18.95,47.99 18.95,47.82 19.11,47.66 19.11,47.49 18.95,47.33 18.95,47.16 19.11,47 19.11,46.83 18.95,46.67 18.95,46.5 19.02,46.42 19.02,46.26 18.95,46.18 18.95,42.71 19.11,42.55 21.29,42.55 21.67,42.17 21.67,41.53 21.29,41.15 19.11,41.15 18.95,40.99 18.95,40.67 19.12,40.5 21.25,40.5 21.66,40.1 21.66,39.49 21.28,39.11 20.39,39.11 20.22,38.94 20.22,38.61 20.38,38.45 21.28,38.45 21.66,38.06 21.66,36.01 21.72,35.94 P1.9
  BOTTOM w0.165: P2.8 22.59,48.67 22.27,48.35 19.33,48.35 18.95,48.73 18.95,49.33 v1(19.29,49.67)
CSI_0_CLK_P: length 31.3
  TOP w0.165: P1.7 21.22,35.94 21.29,36.01 21.29,37.91 21.13,38.08 20.23,38.08 19.85,38.46 19.85,39.09 20.23,39.47 21.13,39.47 21.29,39.64 21.29,39.94 21.1,40.13 18.97,40.13 18.58,40.52 18.58,41.14 18.96,41.52 21.13,41.52 21.3,41.68 21.3,42.01 21.13,42.18 18.96,42.18 18.58,42.56 18.58,49.33 v1(18.24,49.67)
  BOTTOM w0.165: v1(18.24,49.67) 18.58,49.33 18.58,48.58 19.18,47.98 22.27,47.98 22.59,47.67 P2.9
CSI_0_D0_N: length 31.3
  TOP w0.165: v1(17.2,55.67) 16.87,55.33 16.87,55.17 17.03,55 17.03,54.84 16.87,54.67 16.87,54.51 17.03,54.34 17.03,54.18 16.87,54.01 16.87,53.85 17.03,53.68 17.03,53.52 16.87,53.35 16.87,53.19 17.03,53.02 17.03,52.86 16.87,52.69 16.87,52.53 16.94,52.45 16.94,52.29 16.87,52.21 16.87,39.89 20.16,36.6 20.16,36.01 20.22,35.94 P1.3
  BOTTOM w0.165: P2.2 22.59,54.67 22.27,54.35 17.29,54.35 16.86,54.78 16.86,55.33 v1(17.2,55.67)
CSI_0_D0_P: length 31.3
  TOP w0.165: P1.1 19.72,35.94 19.79,36.01 19.79,36.45 16.5,39.74 16.5,55.32 v1(16.15,55.67)
  BOTTOM w0.165: v1(16.15,55.67) 16.5,55.32 16.5,54.63 17.14,53.98 22.27,53.98 22.59,53.67 P2.3
CSI_0_D1_N: length 31.3
  TOP w0.165: P1.15 23.23,35.94 23.16,36.01 23.16,36.88 23.32,37.04 24.38,37.04 24.77,37.42 24.77,38.06 24.38,38.44 23.32,38.44 23.16,38.6 23.16,38.93 23.32,39.1 24.38,39.1 24.77,39.48 24.77,40.12 24.38,40.5 23.32,40.5 23.16,40.66 23.16,40.99 23.32,41.16 24.36,41.16 24.74,41.54 24.74,42.17 24.36,42.55 23.32,42.55 23.16,42.72 23.16,44.3 21.04,46.43 21.04,49.2 21.11,49.28 21.11,49.45 21.04,49.52 21.04,49.69 21.2,49.85 21.2,50.02 21.04,50.18 21.04,50.35 21.2,50.51 21.2,50.68 21.04,50.84 21.04,51.01 21.2,51.17 21.2,51.34 21.04,51.5 21.04,51.67 21.2,51.83 21.2,52 21.04,52.16 21.04,52.33 v1(21.37,52.67)
  BOTTOM w0.165: v1(21.37,52.67) 21.04,52.33 21.04,51.76 21.45,51.35 22.27,51.35 22.59,51.67 P2.5
CSI_0_D1_P: length 31.3
  TOP w0.165: v1(20.33,52.67) 20.67,52.33 20.67,46.27 22.79,44.15 22.79,42.57 23.17,42.19 24.21,42.19 24.37,42.02 24.37,41.69 24.21,41.52 23.17,41.52 22.79,41.14 22.79,40.51 23.17,40.13 24.23,40.13 24.4,39.96 24.4,39.63 24.23,39.47 23.17,39.47 22.79,39.09 22.79,38.45 23.17,38.07 24.23,38.07 24.4,37.91 24.4,37.58 24.23,37.41 23.17,37.41 22.79,37.03 22.79,36.01 22.73,35.94 P1.13
  BOTTOM w0.165: v1(20.33,52.67) 20.67,52.33 20.67,51.61 21.29,50.98 22.27,50.98 22.59,50.67 P2.6
CSI_1_CLK_N: length 21
  TOP w0.165: P1.10 21.72,27.56 21.66,27.49 21.66,26.27 18.95,23.56 18.95,19.3 19.02,19.22 19.02,19.05 18.95,18.98 18.95,18.81 19.11,18.65 19.11,18.48 18.95,18.32 18.95,18.15 19.11,17.99 19.11,17.82 18.95,17.66 18.95,17.49 19.11,17.33 19.11,17.16 18.95,17 18.95,16.83 19.11,16.67 19.11,16.5 18.95,16.34 18.95,16.17 v1(19.29,15.83)
  BOTTOM w0.165: P5.8 22.59,14.83 22.27,14.52 19.37,14.52 18.95,14.94 18.95,15.5 v1(19.29,15.83)
CSI_1_CLK_P: length 21
  TOP w0.165: P1.8 21.22,27.56 21.29,27.49 21.29,26.42 18.58,23.71 18.58,16.17 v1(18.24,15.83)
  BOTTOM w0.165: P5.9 22.59,13.83 22.27,14.15 19.21,14.15 18.58,14.78 18.58,15.5 v1(18.24,15.83)
CSI_1_D0_N: length 21
  TOP w0.165: P1.4 20.22,27.56 20.16,27.49 20.16,27.1 19.42,26.37 18.88,26.37 17.75,27.5 17.52,27.5 17.28,27.27 17.28,27.03 18.42,25.9 18.42,25.36 18.14,25.08 18.14,24.97 18.02,24.86 17.91,24.86 17.79,24.74 17.79,24.51 17.68,24.39 17.44,24.39 17.33,24.27 17.33,24.04 17.21,23.92 16.98,23.92 16.86,23.81 16.86,23.51 17.03,23.35 17.03,23.18 16.86,23.02 16.86,22.85 17.03,22.69 17.03,22.52 16.86,22.36 16.86,22.17 v1(17.2,21.83)
  BOTTOM w0.165: P5.2 22.59,20.83 22.27,20.52 17.27,20.52 16.86,20.93 16.86,21.49 v1(17.2,21.83)
CSI_1_D0_P: length 21
  TOP w0.165: v1(16.15,21.83) 16.49,22.17 16.49,23.96 18.05,25.51 18.05,25.75 16.92,26.88 16.92,27.42 17.37,27.87 17.9,27.87 19.04,26.74 19.27,26.74 19.79,27.26 19.79,27.49 19.72,27.56 P1.2
  BOTTOM w0.165: v1(16.15,21.83) 16.49,21.5 16.49,20.78 17.11,20.15 22.27,20.15 22.59,19.83 P5.3
CSI_1_D1_N: length 21
  TOP w0.165: v1(21.37,18.83) 20.99,19.22 20.99,19.39 21.15,19.55 21.15,19.72 20.99,19.88 20.99,20.05 21.15,20.21 21.15,20.38 20.99,20.54 20.99,20.71 21.15,20.87 21.15,21.04 20.99,21.2 20.99,21.37 21.15,21.53 21.15,21.7 20.99,21.86 20.99,23.18 21.41,23.61 21.64,23.61 23.36,21.89 23.9,21.89 24.35,22.34 24.35,22.88 22.63,24.6 22.63,24.83 23.16,25.36 23.16,27.49 23.23,27.56 P1.16
  BOTTOM w0.165: v1(21.37,18.83) 21.04,18.5 21.04,17.88 21.4,17.52 22.27,17.52 22.59,17.83 P5.5
CSI_1_D1_P: length 21
  TOP w0.165: P1.14 22.73,27.56 22.79,27.49 22.79,25.51 22.26,24.98 22.26,24.44 23.98,22.73 23.98,22.49 23.74,22.26 23.51,22.26 21.8,23.98 21.26,23.98 20.62,23.33 20.62,19.12 v1(20.33,18.83)
  BOTTOM w0.165: v1(20.33,18.83) 20.67,18.5 20.67,17.72 21.24,17.15 22.27,17.15 22.59,16.83 P5.6
CSI_4_CLK_N: length 32.6
  TOP w0.165: P1.45 30.73,35.94 30.67,36.01 30.67,37.97 31.46,38.76 31.46,39.3 30.91,39.86 30.91,40.09 31.14,40.32 31.38,40.32 31.93,39.77 32.47,39.77 32.92,40.22 32.92,40.76 32.42,41.26 32.42,41.5 32.65,41.73 32.88,41.73 33.39,41.23 33.92,41.23 34.37,41.68 34.37,42.21 33.87,42.72 33.87,42.95 34.1,43.18 34.34,43.18 34.84,42.68 35.38,42.68 35.83,43.13 35.83,43.67 35.33,44.17 35.33,44.41 35.56,44.64 35.79,44.64 36.3,44.14 36.84,44.14 37.74,45.05 37.74,46.2 37.82,46.28 37.82,46.45 37.74,46.52 37.74,46.69 37.91,46.85 37.91,47.02 37.74,47.18 37.74,47.35 37.91,47.51 37.91,47.68 37.74,47.84 37.74,48.01 37.91,48.17 37.91,48.34 37.74,48.5 37.74,48.67 37.91,48.83 37.91,49 37.74,49.16 37.74,49.33 v1(38.08,49.67)
  BOTTOM w0.165: P3.8 41.39,48.67 41.07,48.35 37.86,48.35 37.74,48.46 37.74,49.33 v1(38.08,49.67)
CSI_4_CLK_P: length 32.6
  TOP w0.165: P1.43 30.23,35.94 30.3,36.01 30.3,38.12 31.09,38.92 31.09,39.15 30.54,39.7 30.54,40.24 30.99,40.69 31.53,40.69 32.08,40.14 32.31,40.14 32.55,40.37 32.55,40.61 32.05,41.11 32.05,41.65 32.5,42.1 33.03,42.1 33.54,41.59 33.77,41.59 34.01,41.83 34.01,42.06 33.5,42.56 33.5,43.1 33.95,43.55 34.49,43.55 34.99,43.05 35.23,43.05 35.46,43.28 35.46,43.52 34.96,44.02 34.96,44.56 35.41,45.01 35.95,45.01 36.45,44.51 36.68,44.51 37.38,45.2 37.38,49.33 v1(37.04,49.67)
  BOTTOM w0.165: v1(37.04,49.67) 37.38,49.33 37.38,48.31 37.7,47.98 41.07,47.98 41.39,47.67 P3.9
CSI_4_D0_N: length 32.6
  TOP w0.165: P1.39 29.23,35.94 29.16,36.01 29.16,41.51 35.66,48 35.66,52.2 35.73,52.28 35.73,52.45 35.66,52.52 35.66,52.69 35.82,52.85 35.82,53.02 35.66,53.18 35.66,53.35 35.82,53.51 35.82,53.68 35.66,53.84 35.66,54.01 35.82,54.17 35.82,54.34 35.66,54.5 35.66,54.67 35.82,54.83 35.82,55 35.66,55.16 35.66,55.33 v1(35.99,55.67)
  BOTTOM w0.165: P3.2 41.39,54.67 41.07,54.35 36.12,54.35 35.66,54.81 35.66,55.33 v1(35.99,55.67)
CSI_4_D0_P: length 32.6
  TOP w0.165: P1.37 28.73,35.94 28.8,36.01 28.8,41.66 35.29,48.15 35.29,55.33 v1(34.95,55.67)
  BOTTOM w0.165: P3.3 41.39,53.67 41.07,53.98 35.97,53.98 35.29,54.66 35.29,55.33 v1(34.95,55.67)
CSI_4_D1_N: length 32.6
  TOP w0.165: v1(40.17,52.67) 39.83,52.33 39.83,52.16 40,52 40,51.83 39.83,51.67 39.83,51.5 40,51.34 40,51.17 39.83,51.01 39.83,50.84 40,50.68 40,50.51 39.83,50.35 39.83,50.18 40,50.02 40,49.85 39.83,49.69 39.83,49.52 39.91,49.45 39.91,49.28 39.83,49.2 39.83,44.18 38.54,42.88 38.54,42.65 39.2,41.99 39.2,41.46 38.75,41.01 38.21,41.01 37.55,41.66 37.32,41.66 37.08,41.43 37.08,41.19 37.74,40.54 37.74,40 37.29,39.55 36.75,39.55 36.1,40.21 35.86,40.21 35.63,39.97 35.63,39.74 36.2,39.17 36.2,38.63 35.75,38.18 35.21,38.18 34.64,38.75 34.41,38.75 32.17,36.51 32.17,36.01 32.23,35.94 P1.51
  BOTTOM w0.165: P3.5 41.39,51.67 41.07,51.35 40.3,51.35 39.83,51.82 39.83,52.33 v1(40.17,52.67)
CSI_4_D1_P: length 32.6
  TOP w0.165: P1.49 31.73,35.94 31.8,36.01 31.8,36.66 34.25,39.12 34.79,39.12 35.36,38.55 35.6,38.55 35.83,38.78 35.83,39.01 35.26,39.59 35.26,40.12 35.71,40.57 36.25,40.57 36.9,39.92 37.14,39.92 37.37,40.15 37.37,40.39 36.72,41.04 36.72,41.58 37.17,42.03 37.7,42.03 38.36,41.37 38.59,41.37 38.83,41.61 38.83,41.84 38.17,42.5 38.17,43.04 39.46,44.33 39.46,52.33 v1(39.13,52.67)
  BOTTOM w0.165: v1(39.13,52.67) 39.46,52.33 39.46,51.66 40.15,50.98 41.07,50.98 41.39,50.67 P3.6
CSI_6_CLK_N: length 24.8
  TOP w0.165: P1.46 30.73,27.56 30.67,27.49 30.67,26.42 32.16,24.93 35.55,24.93 37.74,22.73 37.74,19.3 37.82,19.22 37.82,19.05 37.74,18.98 37.74,18.81 37.91,18.65 37.91,18.48 37.74,18.32 37.74,18.15 37.91,17.99 37.91,17.82 37.74,17.66 37.74,17.49 37.91,17.33 37.91,17.16 37.74,17 37.74,16.83 37.91,16.67 37.91,16.5 37.74,16.34 37.74,16.17 v1(38.08,15.83)
  BOTTOM w0.165: v1(38.08,15.83) 37.74,15.5 37.74,14.94 38.16,14.52 41.07,14.52 41.39,14.83 P4.8
CSI_6_CLK_P: length 24.8
  TOP w0.165: v1(37.04,15.83) 37.38,16.17 37.38,22.58 35.39,24.56 32,24.56 30.3,26.27 30.3,27.49 30.23,27.56 P1.44
  BOTTOM w0.165: P4.9 41.39,13.83 41.07,14.15 38.01,14.15 37.38,14.78 37.38,15.5 v1(37.04,15.83)
CSI_6_D0_N: length 24.8
  TOP w0.165: P1.40 29.23,27.56 29.16,27.49 29.16,25.56 29.79,24.94 29.79,24.4 28.55,23.17 28.55,22.93 28.79,22.7 29.02,22.7 30.25,23.93 30.79,23.93 31.45,23.28 31.84,23.28 31.92,23.36 32.08,23.36 32.16,23.28 32.32,23.28 32.49,23.44 32.65,23.44 32.82,23.28 32.98,23.28 33.15,23.44 33.31,23.44 33.48,23.28 33.64,23.28 33.81,23.44 33.97,23.44 34.14,23.28 34.3,23.28 34.47,23.44 34.63,23.44 34.8,23.28 34.96,23.28 35.46,22.78 35.46,22.17 v1(35.8,21.83)
  BOTTOM w0.165: P4.2 41.39,20.83 41.07,20.52 35.81,20.52 35.46,20.87 35.46,21.5 v1(35.8,21.83)
CSI_6_D0_P: length 24.8
  TOP w0.165: v1(34.75,21.83) 35.09,22.17 35.09,22.63 34.81,22.91 31.29,22.91 30.64,23.56 30.41,23.56 29.17,22.33 28.63,22.33 28.18,22.78 28.18,23.32 29.42,24.55 29.42,24.79 28.8,25.41 28.8,27.49 28.73,27.56 P1.38
  BOTTOM w0.165: v1(34.75,21.83) 35.09,21.5 35.09,20.71 35.65,20.15 41.07,20.15 41.39,19.83 P4.3
CSI_6_D1_N: length 24.8
  TOP w0.165: v1(40.17,18.83) 39.83,19.17 39.83,19.34 40,19.5 40,19.67 39.83,19.83 39.83,20 40,20.16 40,20.33 39.83,20.49 39.83,20.66 40,20.82 40,20.99 39.83,21.15 39.83,21.32 40,21.48 40,21.65 39.83,21.81 39.83,21.98 39.91,22.05 39.91,22.22 39.83,22.3 39.83,23.05 39.41,23.47 39.41,23.71 40.09,24.39 40.09,24.93 39.64,25.38 39.1,25.38 38.42,24.69 38.18,24.69 37.95,24.93 37.95,25.16 38.62,25.83 38.62,26.37 38.17,26.82 37.63,26.82 36.96,26.15 36.73,26.15 36.32,26.56 32.87,26.56 32.17,27.26 32.17,27.49 32.23,27.56 P1.52
  BOTTOM w0.165: P4.5 41.39,17.83 41.07,17.52 40.16,17.52 39.83,17.84 39.83,18.5 v1(40.17,18.83)
CSI_6_D1_P: length 24.8
  TOP w0.165: v1(39.13,18.83) 39.46,19.17 39.46,22.89 39.04,23.32 39.04,23.86 39.73,24.54 39.73,24.78 39.49,25.01 39.26,25.01 38.57,24.33 38.03,24.33 37.58,24.77 37.58,25.31 38.25,25.98 38.25,26.22 38.02,26.45 37.79,26.45 37.11,25.78 36.58,25.78 36.17,26.19 32.71,26.19 31.8,27.1 31.8,27.49 31.73,27.56 P1.50
  BOTTOM w0.165: P4.6 41.39,16.83 41.07,17.15 40,17.15 39.46,17.69 39.46,18.5 v1(39.13,18.83)
GP2_SCL: length 30.1
  TOP w0.203: v1(44.14,43.67) 46.23,41.57 P1.87
  BOTTOM w0.203: P2.13 25.19,43.67 25.37,43.48 41.18,43.48 41.37,43.67 P3.13 v1(44.14,43.67)
GP2_SDA: length 30.4
  TOP w0.203: P1.89 46.73,41.88 v1(45.95,42.67)
  BOTTOM w0.203: P2.14 25.19,42.67 25.4,42.88 41.16,42.88 41.37,42.67 P3.14 v1(45.95,42.67)
GP4_SCL: length 16
  TOP w0.203: P1.105 50.73,36.56 52.15,37.97 v1(60.43,37.97)
  BOTTOM w0.203: v1(60.43,37.97) 60.88,37.52 60.88,36.03 60.54,35.69 U1.2
GP4_SDA: length 14.9
  TOP w0.203: P1.107 51.23,36.2 52.4,37.36 60.73,37.36 v1(61.49,36.6)
  BOTTOM w0.203: v1(61.49,36.6) 61.49,36.04 61.81,35.73 U1.3
SCL: length 51.7
  BOTTOM w0.203: P5.13 25.19,9.83 25.77,9.25 40.78,9.25 41.37,9.83 P4.13 44.1,9.83 44.88,10.62 44.88,18.8 50.75,24.66 58.6,24.66 60.81,26.87 60.81,27.54 60.54,27.81 U1.7
SDA: length 52.6
  BOTTOM w0.203: U1.6 61.81,27.81 61.49,27.5 61.49,26.75 58.83,24.08 51,24.08 45.52,18.59 45.52,10.37 43.98,8.83 P4.14 41.37,8.83 41.14,8.61 25.41,8.61 25.19,8.83 P5.14
UNNAMED_2_ADG884V2_I42_D1: length 4.4
  TOP w0.254: v1(60.02,27.24) 60.27,27.49 U2.3
  BOTTOM w0.508: v1(60.02,27.24) C1.2 U1.8
UNNAMED_2_ADG884V2_I42_IN1: length 12.4
  TOP w0.203: U2.8 60.27,32.15 60.77,31.65 U2.4 60.77,27.71 R1.1 61.27,26.29 v1(61.82,25.73)
  BOTTOM w0.203: S1.1B v1(61.82,25.73)

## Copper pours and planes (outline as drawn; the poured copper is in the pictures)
GND on TOP, BOTTOM: 14.48,60.96 15.07,62.4 16.51,62.99 57.15,62.99 58.59,62.4 59.18,60.96 59.18,43.18 60.07,41.02 62.23,40.13 71.12,40.13 72.56,39.54 73.15,38.1 73.15,25.4 72.56,23.96 71.12,23.37 62.23,23.37 60.07,22.48 59.18,20.32 59.18,2.54 58.59,1.1 57.15,0.51 16.51,0.51 15.07,1.1 14.48,2.54 14.48,20.32 13.59,22.48 11.43,23.37 2.54,23.37 1.1,23.96 0.51,25.4 0.51,38.1 1.1,39.54 2.54,40.13 11.43,40.13 13.59,41.02 14.48,43.18
GND on L2_GND, L3_GND: 0.51,62.99 73.15,62.99 73.15,0.51 0.51,0.51
VDD_3V3 on TOP: 50.06,29.72 50.06,26.95 50.34,26.67 58.88,26.67 60.45,28.24 60.45,34.01 60.12,34.34 58.8,34.34 58.5,34.04 58.5,31.52 57.23,30.25 50.6,30.25

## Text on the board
Ref Des/Silkscreen Bottom: OFF | TOF | S1 SETUP | RGB | ON | TOF CAMERA ONLY | TOF OR RGB CAMERA
User.45: FIGURE | SIZE | 125.0 | PLATED | NON-PLATED | FINISHED HOLES IN MILS | ALL UNITS ARE IN MILS | QTY | 4 | TOLERANCE/NOTES
